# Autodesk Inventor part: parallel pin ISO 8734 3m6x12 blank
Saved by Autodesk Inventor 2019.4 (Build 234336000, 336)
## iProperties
Created: 2021-08
Part Number: parallel pin ISO 8734 3m6x12 blank
Material: Generic
Document SubType Name: Modeling
Designer: Administrator
Density: 1 g/cm^3
Appearance: Default
Title: parallel pin ISO 8734 3m6x12 Blank
Author: Administrator
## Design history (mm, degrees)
feature "Body1"
body "Solid1"
